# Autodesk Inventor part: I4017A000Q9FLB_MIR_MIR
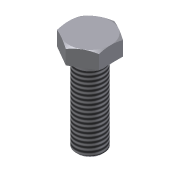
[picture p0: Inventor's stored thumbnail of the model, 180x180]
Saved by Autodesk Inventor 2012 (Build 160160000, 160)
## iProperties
Company: CAD-Verlag
Shininess: 64.0
Length Units: 11269
Angle Units: 11279
Time Units: 11290
Mass Units: 11283
Length Display Precision: 3
Angle Display Precision: 2
Compacted: True
Part Number: I4017A000Q9FLB_MIR_MIR
Document SubType Name: Modeling
Created: 2004-09
Material: Steel, Mild
Designer: Greiling
Manufacturer: Standard
Standards Organization: Custom
Density: 1 g/cm^3
Density: 0.0
Volumn: 0.0
Area: 0.0
PropertySet Name: Model Information
Control State: 0
Master: False
Checked Out: False
Author: Jürgen Kronas
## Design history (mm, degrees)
derived "I4017A000Q9FLB_MIR.ipt" dims "d28" = 0
  node "WorkPlane1"
  node "MSC_PF1"
  node "MSC_PT1"
  node "MSC_A1"
  node "WorkAxis1"
  node "WorkPoint1"
node "Volumenkörper1"
node "Volumenkörpern"
node "Oberflächenkörpern"
tag "Bezeichnung2"
feature "Volumenkörper1::I4017A000Q9FLB_MIR.ipt" dims "d0" = 10, "d28" = 0
